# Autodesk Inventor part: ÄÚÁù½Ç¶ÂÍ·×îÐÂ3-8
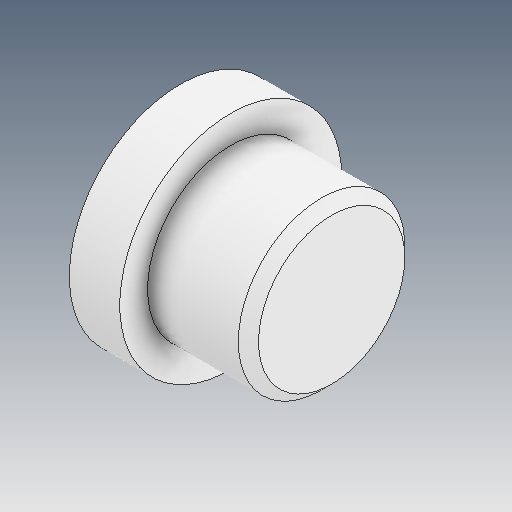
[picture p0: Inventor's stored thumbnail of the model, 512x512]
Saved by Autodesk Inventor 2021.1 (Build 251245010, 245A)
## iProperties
Created: 2021-05
Part Number: ÄÚÁù½Ç¶ÂÍ·×îÐÂ3-8
Material: Ogólny
Document SubType Name: Modeling
Designer: user
Density: 1 g/cm^3
Appearance: Domyślna
Author: user
Revision Number: ÈÎºÎ
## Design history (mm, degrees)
feature "ÊäÈë1"
node "Bryła1"
